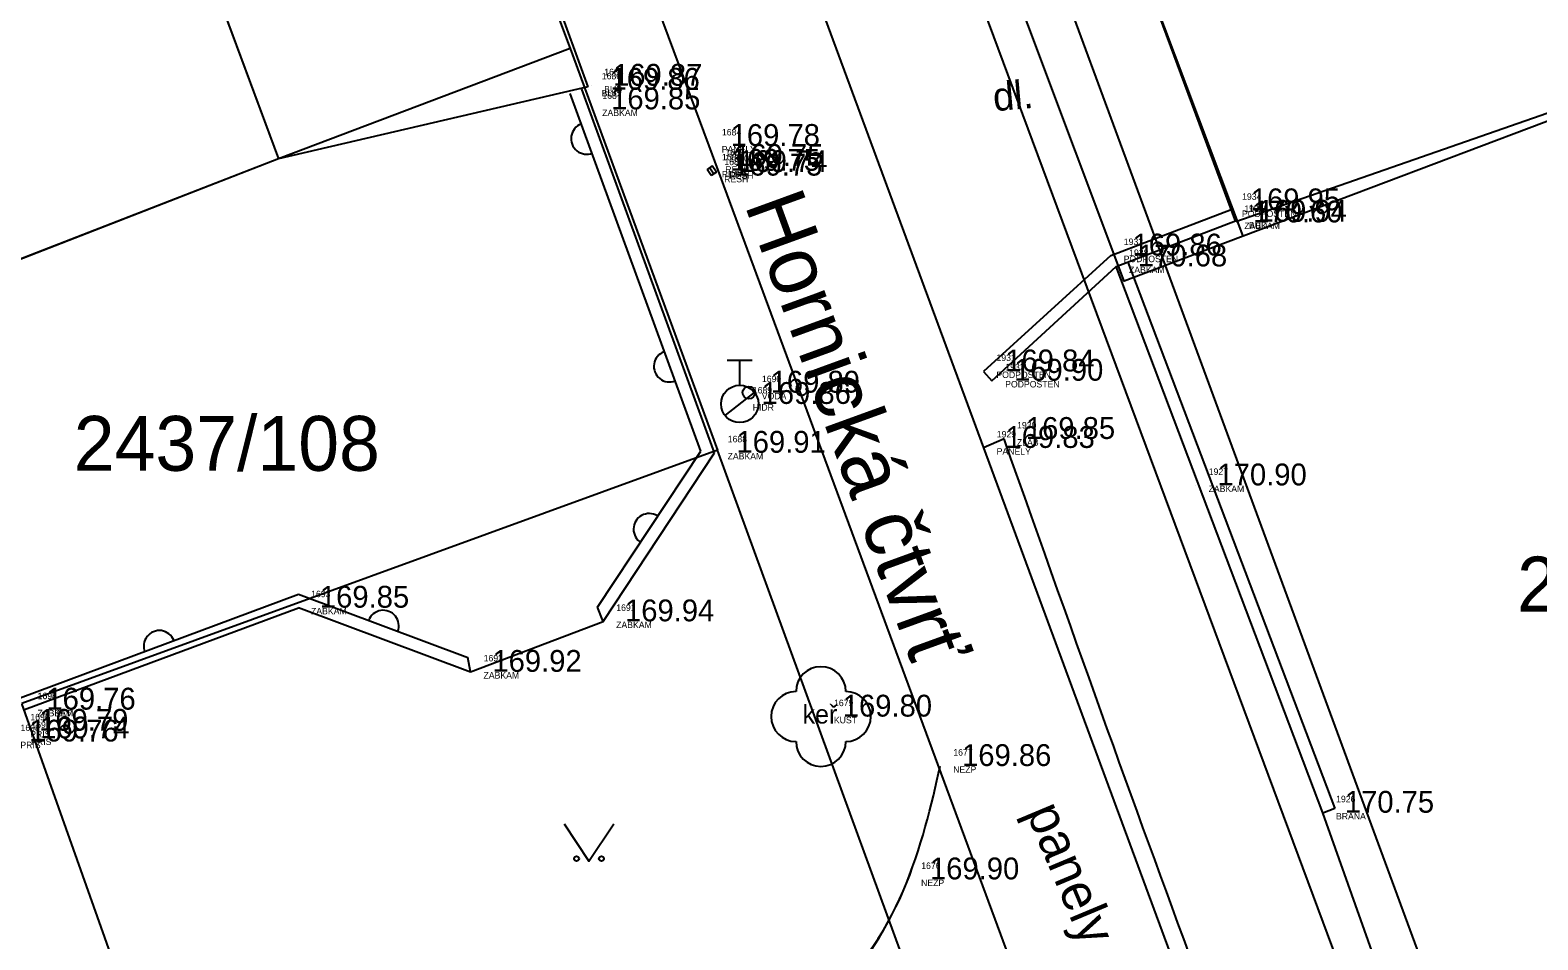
# Model space of a CAD drawing. Extents: x -566117 to -565580, y -1202428 to -1201938.
# Drawn here: x -565922.24 to -565892.03, y -1202102.26 to -1202084.03 of the extents above; entities that cross this region are included whole.
import ezdxf

# ---------------------------------------------------------------- set-up
doc = ezdxf.new("R2010")
doc.units = 0
for name, color, linetype in [('Bod', 7, 'Continuous'), ('BUDOVY_MĚŘ (Construction)', 7, 'Continuous'), ('BUOVY_NEMĚŘ', 7, 'Continuous'), ('CIZÍ_NADZEM', 7, 'Continuous'), ('Implicitní', 7, 'Continuous'), ('Katastr', 7, 'Continuous'), ('Kod', 7, 'Continuous'), ('Oplocení', 7, 'Continuous'), ('POMOC_POPIS', 7, 'Continuous'), ('Voda', 7, 'Continuous'), ('Výška', 7, 'Continuous'), ('ZELEŇ', 7, 'Continuous'), ('ZN_KULTUR', 7, 'Continuous'), ('Zpevněné plohy', 7, 'Continuous'), ('Číslo', 7, 'Continuous')]:
    doc.layers.add(name, color=color, linetype=linetype)

# ---------------------------------------------------------------- blocks, each defined once
blk = doc.blocks.new('A$C69D74C1E')
at = {"layer": 'Katastr'}
for p, q in [((181.01, -66.83), (149.9, 16.82)), ((150.48, -7.82), (153.51, -15.96)), ((144.64, -10.01), (147.66, -18.17)), ((167, -19.72), (164.93, -14.23)), ((165.44, -20.31), (163.41, -14.79)), ((153.51, -15.96), (147.66, -18.17)), ((153.51, -15.96), (156.46, -24.01)), ((147.66, -18.17), (139.61, -21.3)), ((182.39, -66.32), (165.44, -20.31)), ((156.46, -24.01), (142.52, -29.09)), ((161.85, -38.75), (156.46, -24.01)), ((147.79, -43.94), (142.52, -29.09))]:
    blk.add_line(p, q, dxfattribs=at)
for points in [[(165.44, -20.31), (164.61, -20.62), (152.01, 12.96)], [(181.81, -14.13), (178.46, -15.39), (167, -19.72), (165.44, -20.31)]]:
    blk.add_lwpolyline(points, dxfattribs=at)
blk.add_text('Hornická čtvrť', height=1.2, rotation=290, dxfattribs=at).set_placement((156.998, -19.086))
for s, p in [('2437/108', (143.56, -24.423)), ('2437/261', (172.487, -27.243))]:
    blk.add_text(s, height=1.1, dxfattribs=at).set_placement(p)
blk = doc.blocks.new('6.130')
at = {"layer": 'Voda'}
for p, q in [((-0.5, 1.75), (0.5, 1.75)), ((0, 0.75), (0, 1.75)), ((-0.588, -0.462), (0.592, 0.464))]:
    blk.add_line(p, q, dxfattribs=at)
blk.add_circle((0, 0), 0.75, dxfattribs=at)
blk = doc.blocks.new('POINT_DISPLAY')
at = {"layer": 'Implicitní'}
blk.add_line((0, 0), (0, 0), dxfattribs=at)
blk = doc.blocks.new('3.130')
at = {"layer": 'ZELEŇ'}
blk.add_circle((0, 0), 0.001, dxfattribs=at)
for centre, start, end in [((0, 1), 0, 179.99999), ((-1, 0), 89.99999, 269.99999), ((1, 0), 270, 89.99999), ((0, -1), 179.99999, 359.99999)]:
    blk.add_arc(centre, 1, start, end, dxfattribs=at)
blk.add_text('keř', height=0.75, dxfattribs=at).set_placement((-0.737, -0.28))
blk = doc.blocks.new('3.140_2')
at = {"layer": 'ZN_KULTUR'}
blk.add_lwpolyline([(-1, 1.5), (0, 0), (1, 1.5)], dxfattribs=at)
for centre in [(-0.5, 0.1), (0.5, 0.1)]:
    blk.add_circle(centre, 0.1, dxfattribs=at)

msp = doc.modelspace()

# ---------------------------------------------------------------- linework, layer by layer
at = {"layer": 'BUDOVY_MĚŘ (Construction)'}
for p, q in [((-565914.494, -1202075.72), (-565911.07, -1202085.169)), ((-565898.08, -1202087.871), (-565900.763, -1202080.627))]:
    msp.add_line(p, q, dxfattribs=at)
at = {"layer": 'BUOVY_NEMĚŘ'}
msp.add_line((-565911.07, -1202085.169), (-565917.27, -1202086.61), dxfattribs=at)
for points in [[(-565900.763, -1202080.627), (-565889.37, -1202076.13), (-565886.473, -1202083.831), (-565898.08, -1202087.871)], [(-565927.82, -1202083.18), (-565928.47, -1202081.48), (-565926.14, -1202080.62), (-565926.52, -1202079.59), (-565922.76, -1202078.19), (-565922.38, -1202079.22), (-565920.29, -1202078.45), (-565917.27, -1202086.61), (-565925.32, -1202089.74)]]:
    msp.add_lwpolyline(points, dxfattribs=at)
at = {"layer": 'Implicitní'}
for p, q in [((-565908.572, -1202086.753), (-565908.677, -1202086.826)), ((-565908.489, -1202086.874), (-565908.572, -1202086.753)), ((-565908.593, -1202086.946), (-565908.677, -1202086.826)), ((-565908.624, -1202086.789), (-565908.541, -1202086.91)), ((-565908.489, -1202086.874), (-565908.593, -1202086.946))]:
    msp.add_line(p, q, dxfattribs=at)
for points in [[(-565932.951, -1202113.731), (-565927.736, -1202113.122), (-565919.003, -1202112.101), (-565911.071, -1202106.443), (-565906.177, -1202103.795), (-565904.581, -1202101.314), (-565904.179, -1202099.548), (-565904.004, -1202098.78)], [(-565908.87, -1202105.284), (-565907.977, -1202104.787), (-565906.181, -1202103.788), (-565904.581, -1202101.315), (-565904.179, -1202099.549), (-565904.004, -1202098.78)]]:
    msp.add_open_spline(points, degree=3, dxfattribs=at)
at = {"layer": 'Oplocení'}
for p, q in [((-565908.526, -1202092.501), (-565911.187, -1202085.212)), ((-565908.804, -1202092.468), (-565911.422, -1202085.297)), ((-565896.333, -1202099.716), (-565900.48, -1202088.766)), ((-565900.246, -1202088.68), (-565896.098, -1202099.63)), ((-565910.873, -1202095.598), (-565908.804, -1202092.468)), ((-565910.759, -1202095.88), (-565908.526, -1202092.501)), ((-565922.444, -1202097.416), (-565916.864, -1202095.338)), ((-565916.864, -1202095.338), (-565913.472, -1202096.605)), ((-565922.357, -1202097.65), (-565916.865, -1202095.606)), ((-565916.864, -1202095.605), (-565913.418, -1202096.892)), ((-565910.759, -1202095.88), (-565910.873, -1202095.598)), ((-565913.418, -1202096.892), (-565910.759, -1202095.88)), ((-565913.418, -1202096.892), (-565913.472, -1202096.605)), ((-565896.333, -1202099.716), (-565896.099, -1202099.627)), ((-565895.25, -1202102.782), (-565896.333, -1202099.716))]:
    msp.add_line(p, q, dxfattribs=at)
for centre, start, end in [((-565911.09, -1202086.205), 110.5369, 291.6585), ((-565909.43, -1202090.769), 110.5369, 291.6585), ((-565909.838, -1202094.033), 58.4438, 239.5654), ((-565915.168, -1202095.972), 338.5215, 159.6432), ((-565919.654, -1202096.377), 21.8664, 202.988)]:
    msp.add_arc(centre, 0.313, start, end, dxfattribs=at)
at = {"layer": 'Voda'}
msp.add_circle((-565907.84, -1202091.296), 0.125, dxfattribs=at)
at = {"layer": 'Zpevněné plohy'}
for p, q in [((-565912.321, -1202076.456), (-565908.642, -1202086.351)), ((-565908.642, -1202086.351), (-565900.462, -1202108.462)), ((-565900.588, -1202088.547), (-565898.171, -1202087.624)), ((-565900.48, -1202088.766), (-565898.086, -1202087.853)), ((-565900.588, -1202088.547), (-565903.139, -1202090.87)), ((-565902.968, -1202091.057), (-565900.48, -1202088.766)), ((-565903.139, -1202090.87), (-565902.968, -1202091.057)), ((-565902.726, -1202092.224), (-565903.134, -1202092.404)), ((-565903.134, -1202092.404), (-565898.471, -1202105.036))]:
    msp.add_line(p, q, dxfattribs=at)
msp.add_lwpolyline([(-565916.911, -1202055.469), (-565915.451, -1202059.598), (-565912.427, -1202067.771), (-565909.215, -1202076.116), (-565906.527, -1202083.223), (-565903.134, -1202092.404)], dxfattribs=at)
for points in [[(-566046.233, -1202095.491), (-566045.931, -1202095.393), (-566043.978, -1202094.752), (-566040.389, -1202093.195), (-566035.531, -1202091.756), (-566028.975, -1202089.449), (-566022.404, -1202086.74), (-566013.877, -1202083.764), (-566006.988, -1202080.967), (-565999.231, -1202078.336), (-565993.39, -1202076.098), (-565982.391, -1202071.759), (-565967.94, -1202066.641), (-565949.498, -1202059.811), (-565935.388, -1202054.572), (-565926.049, -1202051.077), (-565917.958, -1202048.181), (-565909.827, -1202045.163), (-565898.95, -1202041.321), (-565888.732, -1202037.388), (-565879.759, -1202034.036), (-565869.081, -1202030.224), (-565859.242, -1202026.317), (-565849.297, -1202023.069), (-565843.932, -1202020.848), (-565836.631, -1202018.501), (-565830.04, -1202016.01), (-565822.89, -1202013.251), (-565816.476, -1202011.009), (-565808.989, -1202007.913), (-565802.143, -1202004.887), (-565798.059, -1202002.759), (-565793.947, -1202000.116), (-565789.34, -1201997.072), (-565785.134, -1201994.185), (-565781.539, -1201991.969), (-565778.045, -1201989.73), (-565773.319, -1201986.775), (-565768.281, -1201983.714), (-565761.544, -1201979.725), (-565754.374, -1201977.005), (-565748.201, -1201974.518), (-565743.713, -1201972.786), (-565741.115, -1201971.759), (-565739.444, -1201971.098)], [(-565891.477, -1202122.761), (-565891.53, -1202122.617), (-565892.789, -1202119.18), (-565894.921, -1202113.182), (-565898.82, -1202103.223), (-565901.226, -1202096.449), (-565902.726, -1202092.224)]]:
    msp.add_open_spline(points, degree=3, dxfattribs=at)

# ---------------------------------------------------------------- block references
at = {"layer": 'Bod'}
for p in [(-565911.049, -1202085.225), (-565911, -1202085.144), (-565911.039, -1202085.618), (-565908.642, -1202086.351), (-565908.572, -1202086.753), (-565908.642, -1202086.849), (-565908.593, -1202086.946), (-565908.49, -1202086.875), (-565898.216, -1202087.641), (-565898.171, -1202087.884), (-565898.08, -1202087.871), (-565900.588, -1202088.547), (-565900.48, -1202088.766), (-565903.139, -1202090.87), (-565907.84, -1202091.296), (-565902.962, -1202091.057), (-565908.023, -1202091.522), (-565908.526, -1202092.501), (-565903.134, -1202092.404), (-565902.726, -1202092.224), (-565898.885, -1202093.155), (-565916.874, -1202095.606), (-565910.759, -1202095.88), (-565913.418, -1202096.892), (-565906.395, -1202097.789), (-565904.004, -1202098.78), (-565896.333, -1202099.716), (-565904.647, -1202101.052)]:
    msp.add_blockref('POINT_DISPLAY', p, dxfattribs=at)
at = {"layer": 'CIZÍ_NADZEM', "xscale": 0.5, "yscale": 0.5}
msp.add_blockref('6.130', (-565908.023, -1202091.522), dxfattribs=at)
at = {"layer": 'Implicitní'}
msp.add_blockref('A$C69D74C1E', (-566064.93, -1202068.44), dxfattribs=at)
at = {"layer": 'ZELEŇ', "xscale": 0.5, "yscale": 0.5}
msp.add_blockref('3.130', (-565906.395, -1202097.789), dxfattribs=at)
at = {"layer": 'ZN_KULTUR', "xscale": 0.5, "yscale": 0.5}
msp.add_blockref('3.140_2', (-565911.044, -1202100.687), dxfattribs=at)

# ---------------------------------------------------------------- texts
at = {"layer": 'Kod'}
for s, p in [('BUD', (-565910.79, -1202085.36)), ('BUD', (-565910.74, -1202085.278)), ('ZABKAM', (-565910.779, -1202085.752)), ('PANELY', (-565908.383, -1202086.485)), ('RESH', (-565908.312, -1202086.887)), ('RESH', (-565908.382, -1202086.983)), ('RESH', (-565908.334, -1202087.08)), ('RESH', (-565908.231, -1202087.009)), ('PODPOSTEN', (-565897.957, -1202087.775)), ('ZABKAM', (-565897.911, -1202088.018)), ('BUD', (-565897.82, -1202088.005)), ('PODPOSTEN', (-565900.328, -1202088.681)), ('ZABKAM', (-565900.221, -1202088.9)), ('PODPOSTEN', (-565902.879, -1202091.004)), ('VODA', (-565907.581, -1202091.43)), ('PODPOSTEN', (-565902.703, -1202091.192)), ('HIDR', (-565907.763, -1202091.656)), ('ZABKAM', (-565908.266, -1202092.635)), ('PANELY', (-565902.874, -1202092.539)), ('ZLAB', (-565902.467, -1202092.358)), ('ZABKAM', (-565898.626, -1202093.289)), ('ZABKAM', (-565916.615, -1202095.74)), ('ZABKAM', (-565910.5, -1202096.015)), ('ZABKAM', (-565913.158, -1202097.027)), ('ZABSET', (-565922.098, -1202097.785)), ('ZABKAM', (-565922.096, -1202097.782)), ('KUST', (-565906.136, -1202097.924)), ('PRIS', (-565922.243, -1202098.208)), ('PRIS', (-565922.223, -1202098.36)), ('PRIS', (-565922.44, -1202098.423)), ('NEZP', (-565903.745, -1202098.914)), ('BRANA', (-565896.073, -1202099.85)), ('NEZP', (-565904.388, -1202101.187))]:
    msp.add_text(s, height=0.13, dxfattribs=at).set_placement(p)
at = {"layer": 'POMOC_POPIS'}
for s, height, rotation, p in [('dl.', 0.57, 4.9059, (-565902.924, -1202085.656)), ('panely', 0.75, 292.7197, (-565902.292, -1202099.702))]:
    msp.add_text(s, height=height, rotation=rotation, dxfattribs=at).set_placement(p)
at = {"layer": 'Výška'}
for s, p in [('169.86', (-565910.612, -1202085.225)), ('169.87', (-565910.562, -1202085.144)), ('169.85', (-565910.601, -1202085.618)), ('169.78', (-565908.205, -1202086.351)), ('169.75', (-565908.204, -1202086.849)), ('169.75', (-565908.134, -1202086.753)), ('169.74', (-565908.053, -1202086.875)), ('169.75', (-565908.156, -1202086.946)), ('169.95', (-565897.779, -1202087.641)), ('170.60', (-565897.733, -1202087.884)), ('169.94', (-565897.642, -1202087.871)), ('169.86', (-565900.15, -1202088.547)), ('170.68', (-565900.043, -1202088.766)), ('169.84', (-565902.701, -1202090.87)), ('169.90', (-565902.525, -1202091.057)), ('169.89', (-565907.403, -1202091.296)), ('169.86', (-565907.585, -1202091.522)), ('169.85', (-565902.288, -1202092.224)), ('169.91', (-565908.088, -1202092.501)), ('169.83', (-565902.696, -1202092.404)), ('170.90', (-565898.448, -1202093.155)), ('169.85', (-565916.437, -1202095.606)), ('169.94', (-565910.322, -1202095.88)), ('169.92', (-565912.98, -1202096.892)), ('169.76', (-565921.92, -1202097.65)), ('169.76', (-565921.918, -1202097.648)), ('169.80', (-565905.958, -1202097.789)), ('169.79', (-565922.065, -1202098.074)), ('169.76', (-565922.262, -1202098.289)), ('169.74', (-565922.045, -1202098.226)), ('169.86', (-565903.567, -1202098.78)), ('170.75', (-565895.895, -1202099.716)), ('169.90', (-565904.21, -1202101.052))]:
    msp.add_text(s, height=0.4375, dxfattribs=at).set_placement(p)
at = {"layer": 'Číslo'}
for s, p in [('1686', (-565910.787, -1202085.016)), ('1685', (-565910.738, -1202084.934)), ('1687', (-565910.776, -1202085.408)), ('1684', (-565908.38, -1202086.141)), ('1683', (-565908.31, -1202086.544)), ('1682', (-565908.379, -1202086.64)), ('1681', (-565908.331, -1202086.736)), ('1680', (-565908.228, -1202086.665)), ('1934', (-565897.954, -1202087.431)), ('1935', (-565897.908, -1202087.675)), ('1936', (-565897.817, -1202087.661)), ('1933', (-565900.325, -1202088.337)), ('1928', (-565900.218, -1202088.557)), ('1931', (-565902.877, -1202090.66)), ('1690', (-565907.578, -1202091.086)), ('1932', (-565902.7, -1202090.848)), ('1689', (-565907.76, -1202091.312)), ('1930', (-565902.464, -1202092.014)), ('1688', (-565908.263, -1202092.291)), ('1929', (-565902.871, -1202092.195)), ('1927', (-565898.623, -1202092.945)), ('1693', (-565916.612, -1202095.396)), ('1691', (-565910.497, -1202095.671)), ('1692', (-565913.155, -1202096.683)), ('1695', (-565922.095, -1202097.441)), ('1694', (-565922.093, -1202097.438)), ('1679', (-565906.133, -1202097.58)), ('1698', (-565922.437, -1202098.079)), ('1696', (-565922.24, -1202097.864)), ('1697', (-565922.22, -1202098.016)), ('1677', (-565903.742, -1202098.571)), ('1926', (-565896.07, -1202099.506)), ('1676', (-565904.385, -1202100.843))]:
    msp.add_text(s, height=0.13, dxfattribs=at).set_placement(p)

doc.saveas('drawing.dxf')
